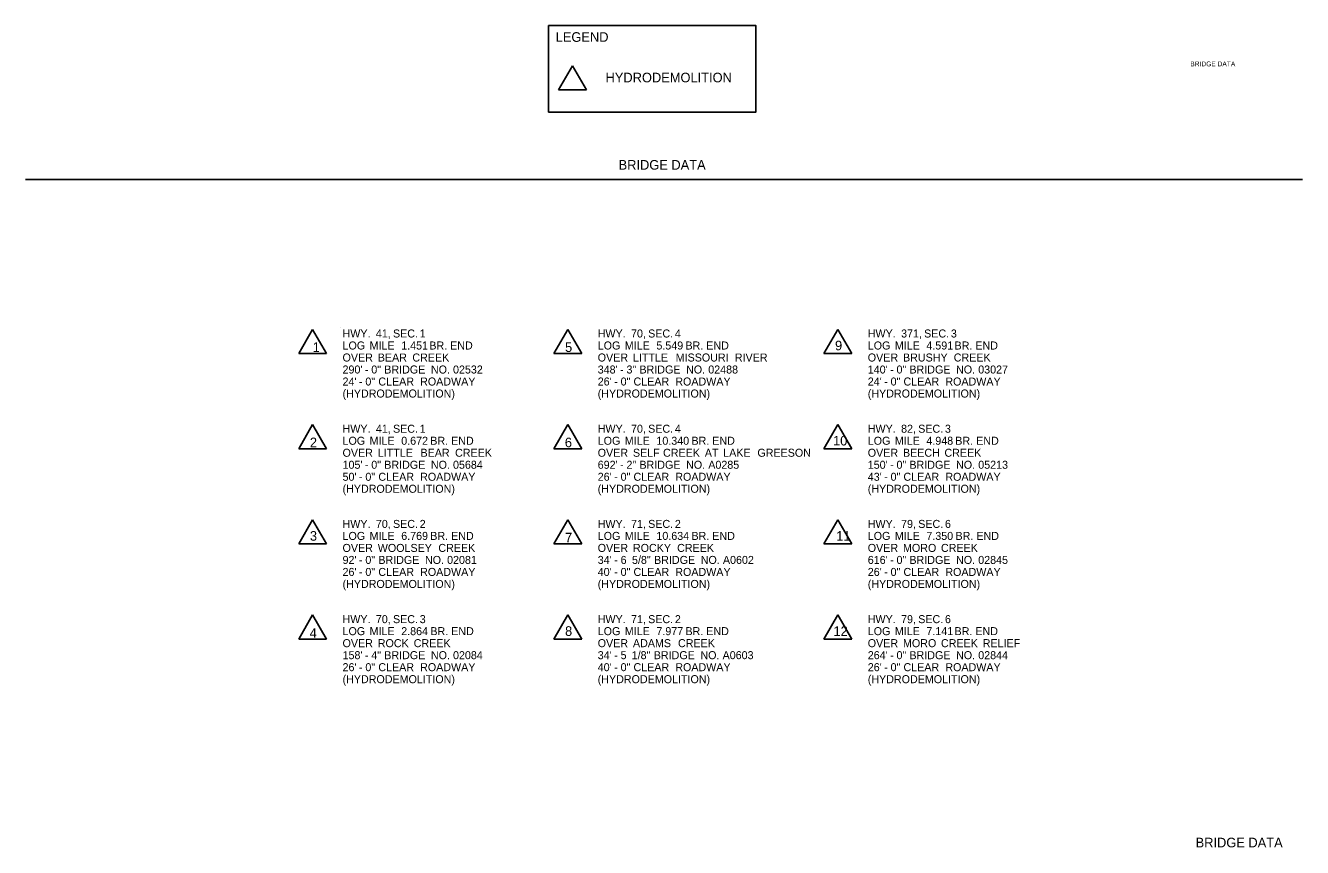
# Model space of a CAD drawing. Extents: x 1930579 to 1933257, y 596452 to 599158.
import ezdxf

# ---------------------------------------------------------------- set-up
doc = ezdxf.new("R2010")
doc.units = 0
for name, color, linetype in [('Default', 7, 'Continuous'), ('R_Border', 7, 'Continuous'), ('R_Border Prem', 7, 'Continuous')]:
    doc.layers.add(name, color=color, linetype=linetype)

msp = doc.modelspace()

# ---------------------------------------------------------------- linework, layer by layer
at = {"layer": 'R_Border'}
for p, q in [((1932345.3, 599107.7), (1932327.9, 599077.6)), ((1932362.7, 599077.6), (1932345.3, 599107.7)), ((1932327.9, 599077.6), (1932362.7, 599077.6)), ((1933257.2, 598965.4), (1931661.8, 598965.4)), ((1932020.5, 598778.2), (1932003.1, 598748.1)), ((1932037.9, 598748.1), (1932020.5, 598778.2)), ((1932055.9, 598780.1), (1932055.9, 598780.1)), ((1932339.3, 598778.2), (1932321.9, 598748.1)), ((1932356.7, 598748.1), (1932339.3, 598778.2)), ((1932676.7, 598778.2), (1932659.2, 598748.1)), ((1932694.1, 598748.1), (1932676.7, 598778.2)), ((1932003.1, 598748.1), (1932037.9, 598748.1)), ((1932321.9, 598748.1), (1932356.7, 598748.1)), ((1932659.2, 598748.1), (1932694.1, 598748.1)), ((1932020.5, 598659.3), (1932003.1, 598629.1)), ((1932037.9, 598629.1), (1932020.5, 598659.3)), ((1932339.3, 598659.3), (1932321.9, 598629.1)), ((1932356.7, 598629.1), (1932339.3, 598659.3)), ((1932676.7, 598659.3), (1932659.2, 598629.1)), ((1932694.1, 598629.1), (1932676.7, 598659.3)), ((1932003.1, 598629.1), (1932037.9, 598629.1)), ((1932321.9, 598629.1), (1932356.7, 598629.1)), ((1932659.2, 598629.1), (1932694.1, 598629.1)), ((1932020.5, 598540.3), (1932003.1, 598510.2)), ((1932037.9, 598510.2), (1932020.5, 598540.3)), ((1932339.3, 598540.3), (1932321.9, 598510.2)), ((1932356.7, 598510.2), (1932339.3, 598540.3)), ((1932676.7, 598540.3), (1932659.2, 598510.2)), ((1932694.1, 598510.2), (1932676.7, 598540.3)), ((1932003.1, 598510.2), (1932037.9, 598510.2)), ((1932321.9, 598510.2), (1932356.7, 598510.2)), ((1932659.2, 598510.2), (1932694.1, 598510.2)), ((1932020.5, 598421.4), (1932003.1, 598391.2)), ((1932037.9, 598391.2), (1932020.5, 598421.4)), ((1932339.3, 598421.4), (1932321.9, 598391.2)), ((1932356.7, 598391.2), (1932339.3, 598421.4)), ((1932676.7, 598421.4), (1932659.2, 598391.2)), ((1932694.1, 598391.2), (1932676.7, 598421.4)), ((1932003.1, 598391.2), (1932037.9, 598391.2)), ((1932321.9, 598391.2), (1932356.7, 598391.2)), ((1932659.2, 598391.2), (1932694.1, 598391.2))]:
    msp.add_line(p, q, dxfattribs=at)
msp.add_lwpolyline([(1932315.4, 599157.9), (1932574.3, 599157.9), (1932574.3, 599049.7), (1932315.4, 599049.7)], close=True, dxfattribs=at)

# ---------------------------------------------------------------- texts
at = {"layer": 'Default'}
for s, p in [('HWY.', (1932057.9, 598768.1)), (' 41,', (1932095.8, 598768.1)), (' SEC.', (1932117.2, 598768.1)), (' 1', (1932150.6, 598768.1)), ('HWY.', (1932376.7, 598768.1)), (' 70,', (1932414.6, 598768.1)), (' SEC.', (1932436, 598768.1)), (' 4', (1932469.4, 598768.1)), ('HWY.', (1932714.1, 598768.1)), (' 371,', (1932752, 598768.1)), (' SEC.', (1932780.8, 598768.1)), (' 3', (1932814.2, 598768.1)), ('LOG', (1932057.9, 598753.1)), (' MILE', (1932088, 598753.1)), (' 1.451', (1932127.5, 598753.1)), (' BR.', (1932162.6, 598753.1)), (' END', (1932188.6, 598753.1)), ('LOG', (1932376.7, 598753.1)), (' MILE', (1932406.8, 598753.1)), (' 5.549', (1932446.3, 598753.1)), (' BR.', (1932482.6, 598753.1)), (' END', (1932508.6, 598753.1)), ('LOG', (1932714.1, 598753.1)), (' MILE', (1932744.2, 598753.1)), (' 4.591', (1932783.6, 598753.1)), (' BR.', (1932818.8, 598753.1)), (' END', (1932844.8, 598753.1)), ('OVER', (1932057.9, 598738.1)), (' BEAR', (1932098.2, 598738.1)), (' CREEK', (1932141.4, 598738.1)), ('OVER', (1932376.7, 598738.1)), (' LITTLE', (1932417, 598738.1)), (' MISSOURI', (1932470.4, 598738.1)), (' RIVER', (1932544.3, 598738.1)), ('OVER', (1932714.1, 598738.1)), (' BRUSHY', (1932754.4, 598738.1)), (' CREEK', (1932817.8, 598738.1)), ("290'", (1932057.9, 598723.1)), (' -', (1932082.1, 598723.1)), (' 0"', (1932090.1, 598723.1)), (' BRIDGE', (1932106.3, 598723.1)), (' NO.', (1932164.6, 598723.1)), (' 02532', (1932192.2, 598723.1)), ("348'", (1932376.7, 598723.1)), (' -', (1932400.9, 598723.1)), (' 3"', (1932408.9, 598723.1)), (' BRIDGE', (1932425.1, 598723.1)), (' NO.', (1932483.4, 598723.1)), (' 02488', (1932511.1, 598723.1)), ("140'", (1932714.1, 598723.1)), (' -', (1932738.3, 598723.1)), (' 0"', (1932746.3, 598723.1)), (' BRIDGE', (1932762.4, 598723.1)), (' NO.', (1932820.7, 598723.1)), (' 03027', (1932848.4, 598723.1)), ("24'", (1932057.9, 598708.1)), (' -', (1932074.7, 598708.1)), (' 0"', (1932082.7, 598708.1)), (' CLEAR', (1932098.9, 598708.1)), (' ROADWAY', (1932151.1, 598708.1)), ("26'", (1932376.7, 598708.1)), (' -', (1932393.5, 598708.1)), (' 0"', (1932401.6, 598708.1)), (' CLEAR', (1932417.7, 598708.1)), (' ROADWAY', (1932469.9, 598708.1)), ("24'", (1932714.1, 598708.1)), (' -', (1932730.9, 598708.1)), (' 0"', (1932738.9, 598708.1)), (' CLEAR', (1932755, 598708.1)), (' ROADWAY', (1932807.3, 598708.1)), ('(HYDRODEMOLITION)', (1932057.9, 598693.1)), ('(HYDRODEMOLITION)', (1932376.7, 598693.1)), ('(HYDRODEMOLITION)', (1932714.1, 598693.1)), ('HWY.', (1932057.9, 598649.1)), (' 41,', (1932095.8, 598649.1)), (' SEC.', (1932117.2, 598649.1)), (' 1', (1932150.6, 598649.1)), ('HWY.', (1932376.7, 598649.1)), (' 70,', (1932414.6, 598649.1)), (' SEC.', (1932436, 598649.1)), (' 4', (1932469.4, 598649.1)), ('HWY.', (1932714.1, 598649.1)), (' 82,', (1932752, 598649.1)), (' SEC.', (1932773.4, 598649.1)), (' 3', (1932806.8, 598649.1)), ('LOG', (1932057.9, 598634.1)), (' MILE', (1932088, 598634.1)), (' 0.672', (1932127.5, 598634.1)), (' BR.', (1932163.8, 598634.1)), (' END', (1932189.8, 598634.1)), ('LOG', (1932376.7, 598634.1)), (' MILE', (1932406.8, 598634.1)), (' 10.340', (1932446.3, 598634.1)), (' BR.', (1932490.1, 598634.1)), (' END', (1932516.1, 598634.1)), ('LOG', (1932714.1, 598634.1)), (' MILE', (1932744.2, 598634.1)), (' 4.948', (1932783.6, 598634.1)), (' BR.', (1932819.7, 598634.1)), (' END', (1932845.8, 598634.1)), ('OVER', (1932057.9, 598619.1)), (' LITTLE', (1932098.2, 598619.1)), (' BEAR', (1932151.6, 598619.1)), (' CREEK', (1932194.8, 598619.1)), ('OVER', (1932376.7, 598619.1)), (' SELF', (1932417, 598619.1)), (' CREEK', (1932454.6, 598619.1)), (' AT', (1932506.8, 598619.1)), (' LAKE', (1932529.8, 598619.1)), (' GREESON', (1932572.5, 598619.1)), ('OVER', (1932714.1, 598619.1)), (' BEECH', (1932754.4, 598619.1)), (' CREEK', (1932806.2, 598619.1)), ("105'", (1932057.9, 598604.1)), (' 0"', (1932090.1, 598604.1)), (' BRIDGE', (1932106.3, 598604.1)), (' NO.', (1932164.6, 598604.1)), (' 05684', (1932192.2, 598604.1)), ("692'", (1932376.7, 598604.1)), (' 2"', (1932408.9, 598604.1)), (' BRIDGE', (1932425.1, 598604.1)), (' NO.', (1932483.4, 598604.1)), (' A0285', (1932511.1, 598604.1)), ("150'", (1932714.1, 598604.1)), (' 0"', (1932746.3, 598604.1)), (' BRIDGE', (1932762.4, 598604.1)), (' NO.', (1932820.7, 598604.1)), (' 05213', (1932848.4, 598604.1)), ("50'", (1932057.9, 598589.1)), (' -', (1932082.1, 598604.1)), (' 0"', (1932082.7, 598589.1)), (' CLEAR', (1932098.9, 598589.1)), (' ROADWAY', (1932151.1, 598589.1)), ("26'", (1932376.7, 598589.1)), (' -', (1932400.9, 598604.1)), (' 0"', (1932401.6, 598589.1)), (' CLEAR', (1932417.7, 598589.1)), (' ROADWAY', (1932469.9, 598589.1)), ("43'", (1932714.1, 598589.1)), (' -', (1932738.3, 598604.1)), (' 0"', (1932738.9, 598589.1)), (' CLEAR', (1932755, 598589.1)), (' ROADWAY', (1932807.3, 598589.1)), ('(HYDRODEMOLITION)', (1932057.9, 598574.1)), (' -', (1932074.7, 598589.1)), ('(HYDRODEMOLITION)', (1932376.7, 598574.1)), (' -', (1932393.5, 598589.1)), ('(HYDRODEMOLITION)', (1932714.1, 598574.1)), (' -', (1932730.9, 598589.1)), ('HWY.', (1932057.9, 598530.2)), (' 70,', (1932095.8, 598530.2)), (' SEC.', (1932117.2, 598530.2)), (' 2', (1932150.6, 598530.2)), ('HWY.', (1932376.7, 598530.2)), (' 71,', (1932414.6, 598530.2)), (' SEC.', (1932436, 598530.2)), (' 2', (1932469.4, 598530.2)), ('HWY.', (1932714.1, 598530.2)), (' 79,', (1932752, 598530.2)), (' SEC.', (1932773.4, 598530.2)), (' 6', (1932806.8, 598530.2)), ('LOG', (1932057.9, 598515.2)), (' MILE', (1932088, 598515.2)), (' 6.769', (1932127.5, 598515.2)), (' BR.', (1932163.8, 598515.2)), (' END', (1932189.8, 598515.2)), ('LOG', (1932376.7, 598515.2)), (' MILE', (1932406.8, 598515.2)), (' 10.634', (1932446.3, 598515.2)), (' BR.', (1932490.1, 598515.2)), (' END', (1932516.1, 598515.2)), ('LOG', (1932714.1, 598515.2)), (' MILE', (1932744.2, 598515.2)), (' 7.350', (1932783.6, 598515.2)), (' BR.', (1932820, 598515.2)), (' END', (1932846.1, 598515.2)), ('OVER', (1932057.9, 598500.2)), (' WOOLSEY', (1932098.2, 598500.2)), (' CREEK', (1932173.9, 598500.2)), ('OVER', (1932376.7, 598500.2)), (' ROCKY', (1932417, 598500.2)), (' CREEK', (1932472.2, 598500.2)), ('OVER', (1932714.1, 598500.2)), (' MORO', (1932754.4, 598500.2)), (' CREEK', (1932801.8, 598500.2)), ("92'", (1932057.9, 598485.2)), (' -', (1932074.7, 598485.2)), (' 0"', (1932082.7, 598485.2)), (' BRIDGE', (1932098.9, 598485.2)), (' NO.', (1932157.2, 598485.2)), (' 02081', (1932184.8, 598485.2)), ("34'", (1932376.7, 598485.2)), (' -', (1932393.5, 598485.2)), (' 6', (1932401.6, 598485.2)), ('  5/8"', (1932412.1, 598485.2)), (' BRIDGE', (1932443.4, 598485.2)), (' NO.', (1932501.7, 598485.2)), (' A0602', (1932529.4, 598485.2)), ("616'", (1932714.1, 598485.2)), (' -', (1932738.3, 598485.2)), (' 0"', (1932746.3, 598485.2)), (' BRIDGE', (1932762.4, 598485.2)), (' NO.', (1932820.7, 598485.2)), (' 02845', (1932848.4, 598485.2)), ("26'", (1932057.9, 598470.2)), (' -', (1932074.7, 598470.2)), (' 0"', (1932082.7, 598470.2)), (' CLEAR', (1932098.9, 598470.2)), (' ROADWAY', (1932151.1, 598470.2)), ("40'", (1932376.7, 598470.2)), (' -', (1932393.5, 598470.2)), (' 0"', (1932401.6, 598470.2)), (' CLEAR', (1932417.7, 598470.2)), (' ROADWAY', (1932469.9, 598470.2)), ("26'", (1932714.1, 598470.2)), (' -', (1932730.9, 598470.2)), (' 0"', (1932738.9, 598470.2)), (' CLEAR', (1932755, 598470.2)), (' ROADWAY', (1932807.3, 598470.2)), ('(HYDRODEMOLITION)', (1932057.9, 598455.2)), ('(HYDRODEMOLITION)', (1932376.7, 598455.2)), ('(HYDRODEMOLITION)', (1932714.1, 598455.2)), ('HWY.', (1932057.9, 598411.2)), (' 70,', (1932095.8, 598411.2)), (' SEC.', (1932117.2, 598411.2)), (' 3', (1932150.6, 598411.2)), ('HWY.', (1932376.7, 598411.2)), (' 71,', (1932414.6, 598411.2)), (' SEC.', (1932436, 598411.2)), (' 2', (1932469.4, 598411.2)), ('HWY.', (1932714.1, 598411.2)), (' 79,', (1932752, 598411.2)), (' SEC.', (1932773.4, 598411.2)), (' 6', (1932806.8, 598411.2)), ('LOG', (1932057.9, 598396.2)), (' MILE', (1932088, 598396.2)), (' 2.864', (1932127.5, 598396.2)), (' BR.', (1932163.9, 598396.2)), (' END', (1932189.9, 598396.2)), ('LOG', (1932376.7, 598396.2)), (' MILE', (1932406.8, 598396.2)), (' 7.977', (1932446.3, 598396.2)), (' BR.', (1932482.6, 598396.2)), (' END', (1932508.6, 598396.2)), ('LOG', (1932714.1, 598396.2)), (' MILE', (1932744.2, 598396.2)), (' 7.141', (1932783.6, 598396.2)), (' BR.', (1932818.8, 598396.2)), (' END', (1932844.8, 598396.2)), ('OVER', (1932057.9, 598381.2)), (' ROCK', (1932098.2, 598381.2)), (' CREEK', (1932143.1, 598381.2)), ('OVER', (1932376.7, 598381.2)), (' ADAMS', (1932417, 598381.2)), (' CREEK', (1932473.3, 598381.2)), ('OVER', (1932714.1, 598381.2)), (' MORO', (1932754.4, 598381.2)), (' CREEK', (1932801.8, 598381.2)), (' RELIEF', (1932854, 598381.2)), ("158'", (1932057.9, 598366.2)), (' -', (1932082.1, 598366.2)), (' 4"', (1932090.1, 598366.2)), (' BRIDGE', (1932106.3, 598366.2)), (' NO.', (1932164.6, 598366.2)), (' 02084', (1932192.2, 598366.2)), ("34'", (1932376.7, 598366.2)), (' -', (1932393.5, 598366.2)), (' 5', (1932401.6, 598366.2)), ('  1/8"', (1932411.7, 598366.2)), (' BRIDGE', (1932443, 598366.2)), (' NO.', (1932501.3, 598366.2)), (' A0603', (1932529, 598366.2)), ("264'", (1932714.1, 598366.2)), (' -', (1932738.3, 598366.2)), (' 0"', (1932746.3, 598366.2)), (' BRIDGE', (1932762.4, 598366.2)), (' NO.', (1932820.7, 598366.2)), (' 02844', (1932848.4, 598366.2)), ("26'", (1932057.9, 598351.2)), (' -', (1932074.7, 598351.2)), (' 0"', (1932082.7, 598351.2)), (' CLEAR', (1932098.9, 598351.2)), (' ROADWAY', (1932151.1, 598351.2)), ("40'", (1932376.7, 598351.2)), (' -', (1932393.5, 598351.2)), (' 0"', (1932401.6, 598351.2)), (' CLEAR', (1932417.7, 598351.2)), (' ROADWAY', (1932469.9, 598351.2)), ("26'", (1932714.1, 598351.2)), (' -', (1932730.9, 598351.2)), (' 0"', (1932738.9, 598351.2)), (' CLEAR', (1932755, 598351.2)), (' ROADWAY', (1932807.3, 598351.2)), ('(HYDRODEMOLITION)', (1932057.9, 598336.2)), ('(HYDRODEMOLITION)', (1932376.7, 598336.2)), ('(HYDRODEMOLITION)', (1932714.1, 598336.2))]:
    msp.add_text(s, height=10, rotation=360, dxfattribs=at).set_placement(p)
at = {"layer": 'R_Border'}
for s, p in [('LEGEND', (1932324.2, 599137.5)), ('HYDRODEMOLITION', (1932386.5, 599086.9)), ('BRIDGE DATA', (1932402.8, 598977.8)), ('1', (1932020.5, 598750)), ('5', (1932335.9, 598750)), ('9', (1932673.2, 598752.1)), ('2', (1932017.1, 598631)), ('6', (1932335.6, 598631)), ('10', (1932670.7, 598633.2)), ('3', (1932017.1, 598514.2)), ('7', (1932335.9, 598512.1)), ('11', (1932674.7, 598514.2)), ('4', (1932016.8, 598392.9)), ('8', (1932335.9, 598395.3)), ('12', (1932671.3, 598395.3)), ('BRIDGE DATA', (1933123.7, 598131.1))]:
    msp.add_text(s, height=12, rotation=360, dxfattribs=at).set_placement(p)
at = {"layer": 'R_Border Prem'}
msp.add_text('BRIDGE DATA', height=6, rotation=360, dxfattribs=at).set_placement((1933117.1, 599106.9))

doc.saveas('drawing.dxf')
